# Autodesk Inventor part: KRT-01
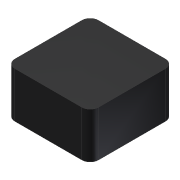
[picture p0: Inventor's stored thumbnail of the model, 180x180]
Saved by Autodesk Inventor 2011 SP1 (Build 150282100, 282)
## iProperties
Created: 2011-02
Part Number: KRT-01
Material: Rubber
Document SubType Name: Modeling
Designer: SERGIO
Mass: 256.975 g
Surface Area: 545.342 cm^2
Volume: 276.317 cm^3
Density: 0.93 g/cm^3
Author: SERGIO
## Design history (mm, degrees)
sketch "Sketch1"
  geometry: L1 (50, -44)-(50, 44) reference; L2 (44, 50)-(-44, 50) reference; L3 (-50, 44)-(-50, -44) reference; L4 (-44, -50)-(44, -50) reference; L5 (44, -55)-(-44, -55); L6 (-55, -44)-(-55, 44); L7 (-44, 55)-(44, 55); L8 (55, 44)-(55, -44); A1 r 6 centre (44, 44) between (50, 44) and (44, 50) reference; A2 r 6 centre (-44, 44) between (-44, 50) and (-50, 44) reference; A3 r 6 centre (-44, -44) between (-50, -44) and (-44, -50) reference; A4 r 6 centre (44, -44) between (44, -50) and (50, -44) reference; A5 r 11 centre (-44, -44) between (-55, -44) and (-44, -55); A6 r 11 centre (-44, 44) between (-44, 55) and (-55, 44); A7 r 11 centre (44, 44) between (55, 44) and (44, 55); A8 r 11 centre (44, -44) between (44, -55) and (55, -44); 1 further point
  constraints: 16 end point, 16 point on circle, 8 centre point, 2 horizontal, 2 vertical, 23 other
  dimensions: "d0" = 5 distance between parallel lines of L4 L5
extrude "Extrusion1" new body sketch "Sketch1" distance "d1" = 15; taper "d3" = 0 deg; dims "d2" = 40, "d4" = 0
extrude "Extrusion2" join sketch "Sketch1" stored distance "d5" = 20; taper "d6" = 0 deg
body "Solid1"
